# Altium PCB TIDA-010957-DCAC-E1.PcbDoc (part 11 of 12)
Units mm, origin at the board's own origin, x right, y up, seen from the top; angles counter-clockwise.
Board outline 300 x 300 mm, 4 copper layers (Top Layer, Layer 1, Layer 2, Bottom Layer), stack 1.787 mm thick; 1159 components, 619 nets, 3431 pads, 2942 vias.
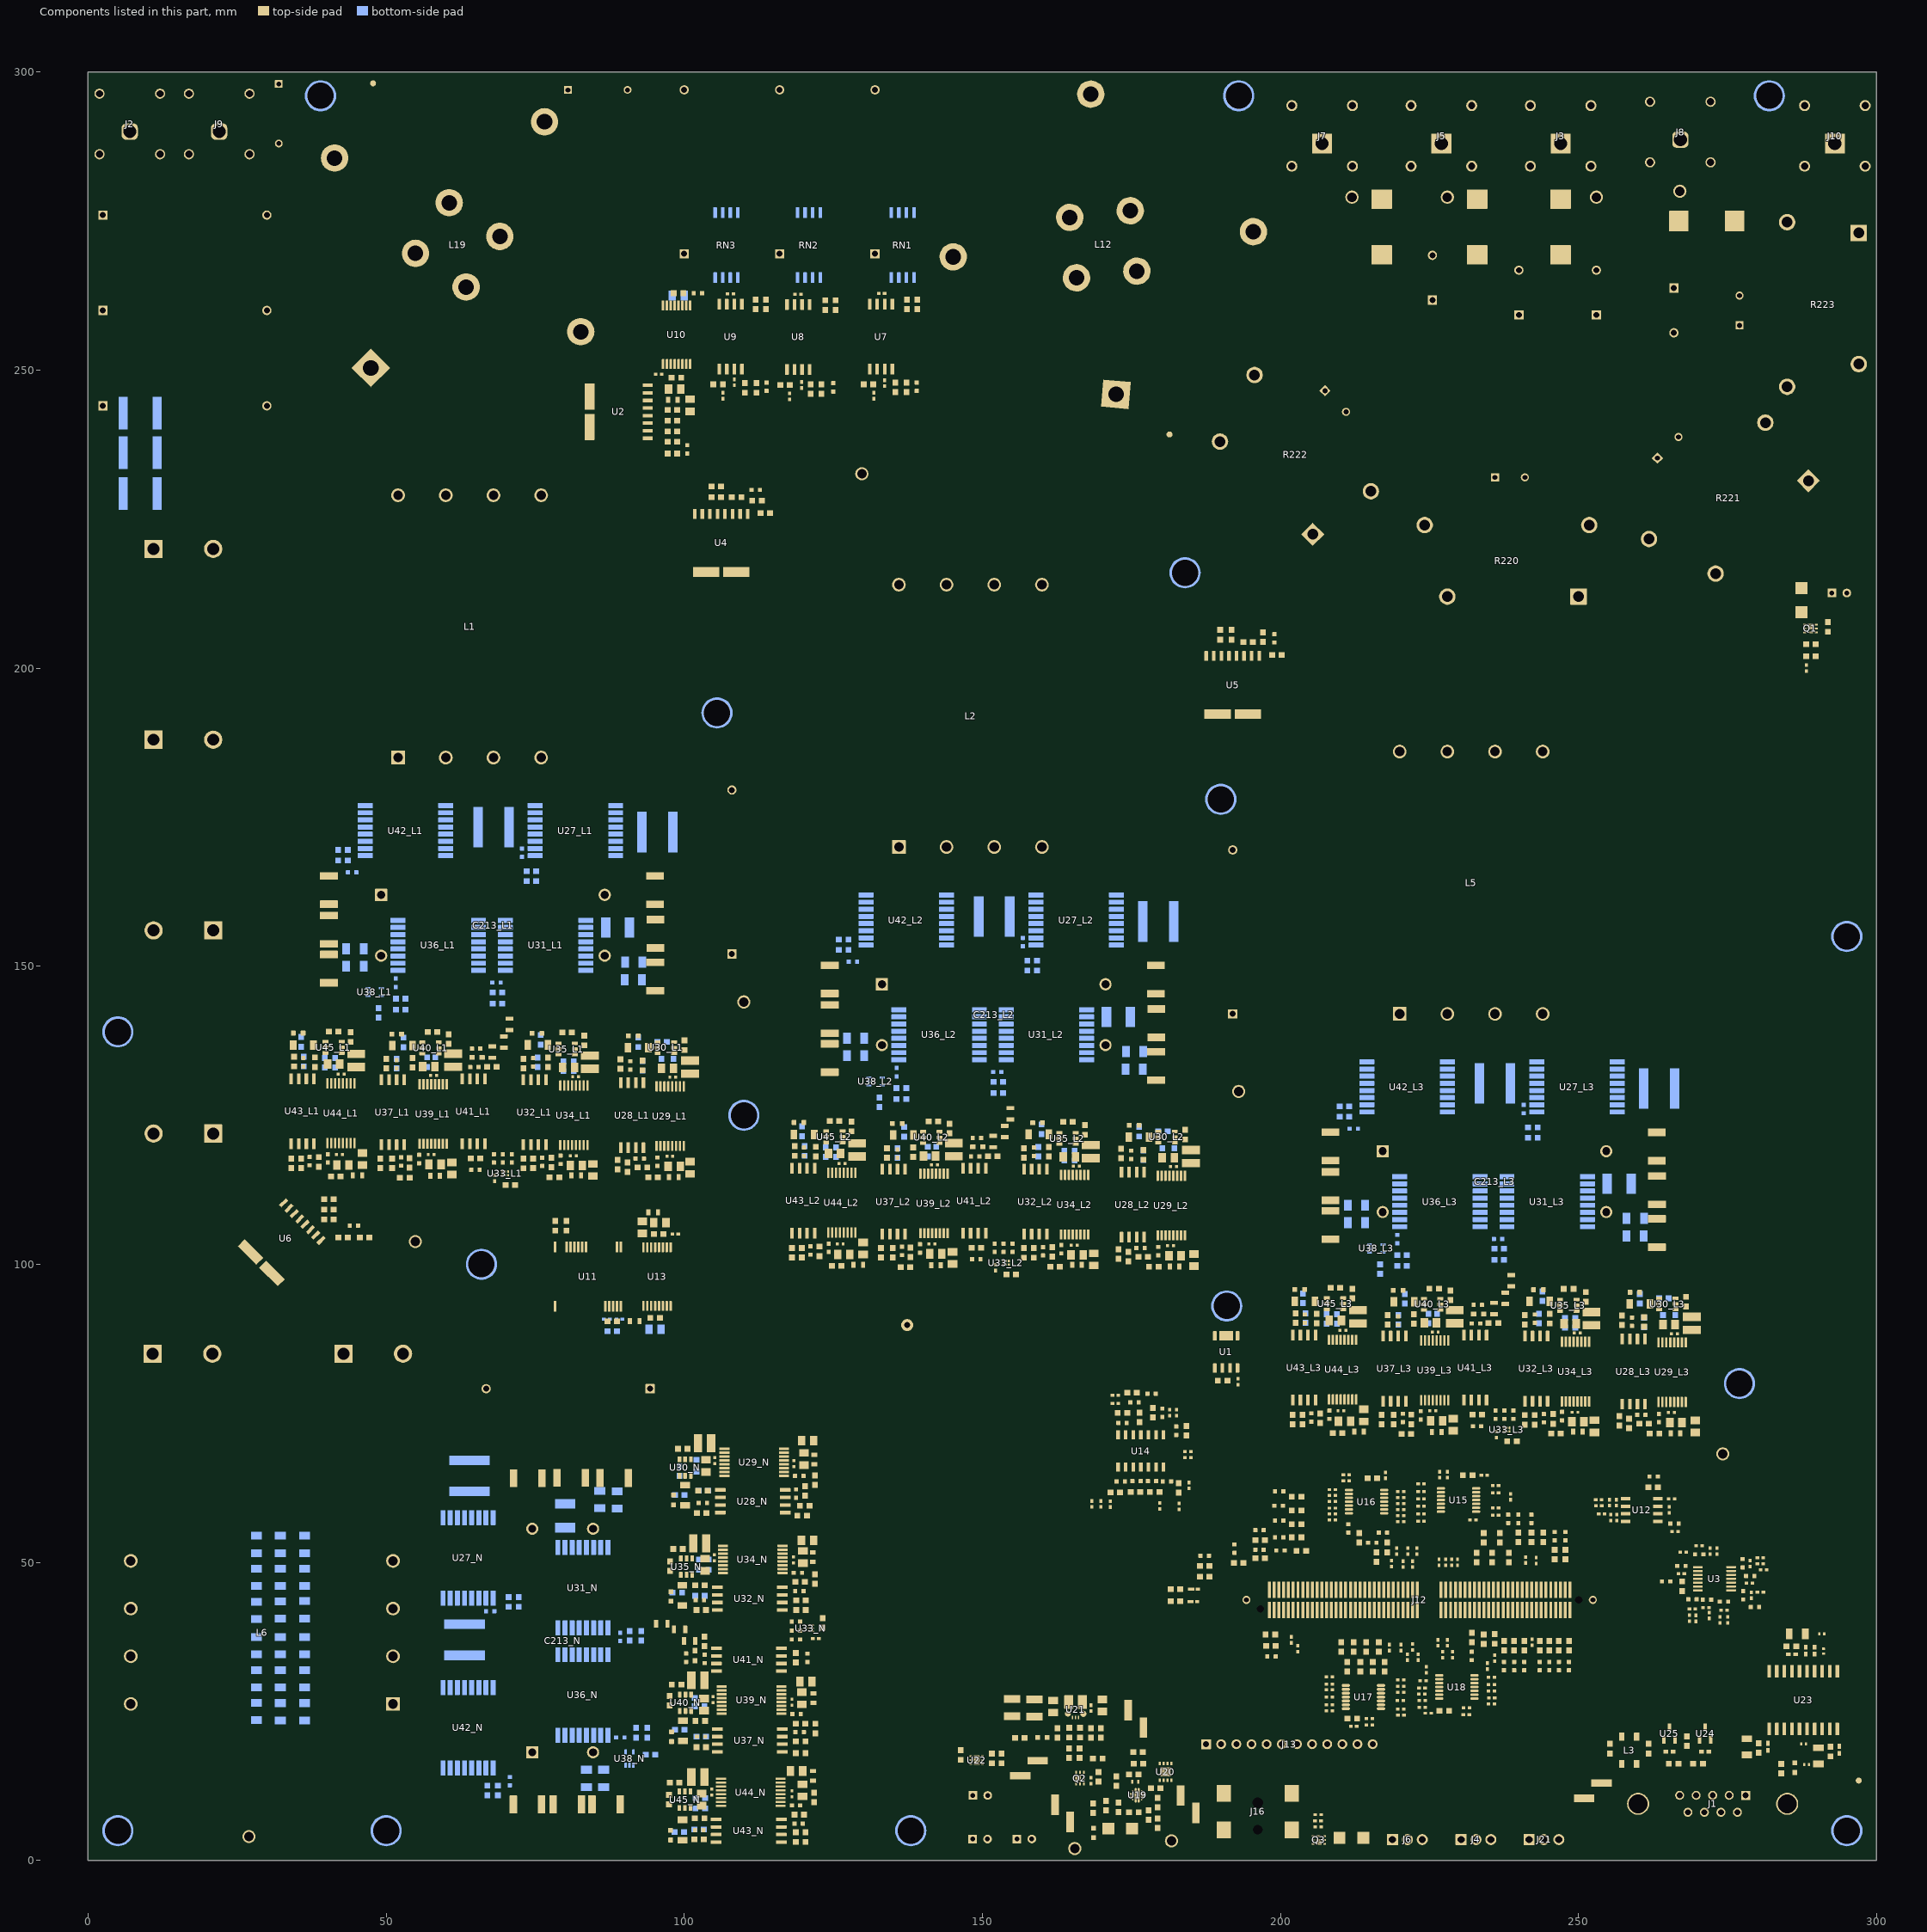
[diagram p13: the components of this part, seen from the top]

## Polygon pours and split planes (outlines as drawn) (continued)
NetC213_L1_2 on Bottom Layer "NONET_L-01_P-001" (solid, pour order 326): 88.1,159.3 88.1,153.9 87.8,153.6 85.6,153.6 85.6,159.3
VDC+ on Bottom Layer "NONET_L-01_P-001" (solid, pour order 325): 91.6,179.5 93.6,179.5 93.9,179.2 93.9,168.7 93.8,168.6 91.5,168.6
NetC213_L1_2 on Bottom Layer "NONET_L-01_P-001" (solid, pour order 324): 70.1,179 69.8,178.7 69.8,170.2 70.1,169.9 71.3,169.9 73.5,172.1 73.5,179
NetC213_L1_1 on Bottom Layer "NONET_L-01_P-001" (solid, pour order 323): 63.6,179 66,179 66.6,178.4 66.6,169.1 63.6,166.1
I_PCC_L3- on Bottom Layer "BOTTOM_LAYER_I_PCC_L3-_P316" (solid, remove dead copper, pour order 316): 194.1,187 193.7,187.4 192.6,187.4 192.6,192.4 194.1,192.4 250.1,192.4 250.1,183.9 194.1,183.9
GND on Bottom Layer "NONET_L-01_P-001" (solid, pour order 311): 42 vertices, not listed, extent 92.9,72.7 299.7,275.5
NetMP12_1 on Bottom Layer "BOTTOM_LAYER_NETMP12_1_P129" (solid, remove dead copper, pour order 129): 187.9,88.4 187.9,97.3 193.9,97.3 193.9,88.4
VDC-_REF on Bottom Layer "NONET_L-01_P-001" (solid, pour order 317): 26.5,23 27.6,24.1 38,24.1 43.8,18.3 56.4,18.3 57.9,16.8 57.9,11.9 57,11 27.6,11 26.5,12.1
GRID_GND on Bottom Layer "NONET_L-01_P-001" (solid, pour order 315): 277.5,299.8 295.9,299.8 299.2,296.5 299.2,281 298.5,280.3 278.4,280.3 276.4,282.3 276.4,298.7
I_PCC_L2- on Bottom Layer "BOTTOM_LAYER_I_PCC_L2-_P314" (solid, remove dead copper, pour order 314): 106.6,216.5 118,216.5 119,217.5 162.6,217.5 162.6,211 106.6,211
NetL12_4 on Bottom Layer "BOTTOM_LAYER_NETL12_4_P082" (solid, remove dead copper, pour order 82): 257,224 257,220 260.5,216.5 272,228 249,251 232,251 198,285 177,285 172,280 172,273 188.9,273 193.5,277.6 198.8,277.6 235.4,241 240,241
NetL12_2 on Bottom Layer "BOTTOM_LAYER_NETL12_2_P081" (solid, remove dead copper, pour order 81): 172.5,263 172.5,270 201,270 237,234 237,221.5 220.5,221.5 220.5,241.5 199,263
I_PCC_L3+ on Bottom Layer "BOTTOM_LAYER_I_PCC_L3+_P059" (solid, remove dead copper, pour order 59): 19 vertices, not listed, extent 34,184.5 192,243
VDC-_REF on Bottom Layer "BOTTOM_LAYER_VDC-_REF_P047" (solid, remove dead copper, pour order 47): 63.5,14 64,13.5 64,9.5 57.5,9.5 56,11 56,18.3 63.5,18.3
NetC213_L2_1 on Bottom Layer "BOTTOM_LAYER_NETC213_L2_1_P219" (solid, remove dead copper, pour order 219): 131,135 131,134 130,134 130,135.5 130,147.5 132,149.5 137.5,149.5 140,152 140,163 141,164 149,164 149.995,163.005 149.995,153.495 140,143.5 140,135
SN_L2 on Bottom Layer "BOTTOM_LAYER_SN_L2_P220" (solid, remove dead copper, pour order 220): 148,148.5 155,148.5 157.9,145.6 157.9,133.5 145.8,133.5 145.8,146.3
NetC213_L2_2 on Bottom Layer "BOTTOM_LAYER_NETC213_L2_2_P221" (solid, remove dead copper, pour order 221): 18 vertices, not listed, extent 154.191,133.356 172.5,164
VDC+ on Bottom Layer "BOTTOM_LAYER_VDC+_P222" (solid, remove dead copper, pour order 222): 171.5,164.5 177.5,164.5 177.5,154.508 179,153.008 179,148 174.6,148 169.3,153.3 169.3,162.3
NetC213_L2_2 on Bottom Layer "BOTTOM_LAYER_NETC213_L2_2_P223" (solid, remove dead copper, pour order 223): 173.244,131.265 174.732,131.265 174.724,131.273 174.724,137.622 172.611,137.622 172.25,137.983 171.659,137.392 171.659,134.703 170.733,133.776
NetD8_L2_2 on Bottom Layer "BOTTOM_LAYER_NETD8_L2_2_P224" (solid, remove dead copper, pour order 224): 177.87,136.861 177.87,132.515 177.876,132.521 182.163,132.521 182.163,131.53 182.118,131.575 176.231,131.575 176.231,136.823 176.269,136.861
NetC213_L2_1 on Bottom Layer "BOTTOM_LAYER_NETC213_L2_1_P225" (solid, remove dead copper, pour order 225): 174,144.5 176.5,144.5 176.5,139 174,139
VDC-_REF on Bottom Layer "BOTTOM_LAYER_VDC-_REF_P226" (solid, remove dead copper, pour order 226): 181.5,164 186.4,164 186.4,153.5 181.5,153.5
NetD13_L2_1 on Bottom Layer "BOTTOM_LAYER_NETD13_L2_1_P227" (solid, remove dead copper, pour order 227): 128,139.5 126.5,139.5 126.5,131.5 128,131.5
VDC-_REF on Bottom Layer "BOTTOM_LAYER_VDC-_REF_P228" (solid, remove dead copper, pour order 228): 129,158 128.5,157.5 124.5,157.5 124.5,164 126,165.5 133.3,165.5 133.3,158
+12V_OUT on Bottom Layer "NONET_L-01_P-001" (solid, pour order 295): 178.3,24.4 179.8,22.9 179.8,16.5 182,14.3 182,11.5 178.594,8.094 168.8,8.094 168.8,24.4
VDC-_REF on Bottom Layer "BOTTOM_LAYER_VDC-_REF_P273" (solid, remove dead copper, pour order 273): 213,130 212.5,129.5 208.5,129.5 208.5,136 210,137.5 217.2,137.5 217.2,130
NetD13_L3_1 on Bottom Layer "BOTTOM_LAYER_NETD13_L3_1_P272" (solid, remove dead copper, pour order 272): 212,111.5 210.5,111.5 210.5,103.5 212,103.5
VDC-_REF on Bottom Layer "BOTTOM_LAYER_VDC-_REF_P271" (solid, remove dead copper, pour order 271): 265.5,136 271.2,136 271.2,125.5 265.5,125.5
NetC213_L3_1 on Bottom Layer "BOTTOM_LAYER_NETC213_L3_1_P270" (solid, remove dead copper, pour order 270): 258,116.5 260.5,116.5 260.5,111 258,111
NetD8_L3_2 on Bottom Layer "BOTTOM_LAYER_NETD8_L3_2_P269" (solid, remove dead copper, pour order 269): 261.87,108.861 261.87,104.515 261.876,104.521 266.163,104.521 266.163,103.53 266.118,103.575 260.231,103.575 260.231,108.823 260.269,108.861
NetC213_L3_2 on Bottom Layer "BOTTOM_LAYER_NETC213_L3_2_P268" (solid, remove dead copper, pour order 268): 257.244,103.265 258.732,103.265 258.724,103.273 258.724,109.622 256.611,109.622 256.25,109.983 255.659,109.392 255.659,106.703 254.733,105.776
VDC+ on Bottom Layer "BOTTOM_LAYER_VDC+_P267" (solid, remove dead copper, pour order 267): 254.4,136.5 261.5,136.5 261.5,126.508 263,125.008 263,120 259.476,120 253.3,126.176 253.3,135.4
NetC213_L3_2 on Bottom Layer "BOTTOM_LAYER_NETC213_L3_2_P266" (solid, remove dead copper, pour order 266): 18 vertices, not listed, extent 238.191,105.356 256.5,136
SN_L3 on Bottom Layer "BOTTOM_LAYER_SN_L3_P265" (solid, remove dead copper, pour order 265): 232,120.5 239,120.5 242,117.5 242,105.5 229.9,105.5 229.9,118.4
NetC213_L3_1 on Bottom Layer "BOTTOM_LAYER_NETC213_L3_1_P264" (solid, remove dead copper, pour order 264): 215,107 215,106 214,106 214,107.5 214,119.5 216,121.5 221.5,121.5 224,124 224,135 225,136 233,136 233.995,135.005 233.995,125.495 223.5,115 223.5,107
VDC-_REF on Bottom Layer "BOTTOM_LAYER_VDC-_REF_P188" (solid, remove dead copper, pour order 188): 45,173 44.5,172.5 40.5,172.5 40.5,179 41.6,180.1 49.3,180.1 49.3,173
NetD13_L1_1 on Bottom Layer "BOTTOM_LAYER_NETD13_L1_1_P187" (solid, remove dead copper, pour order 187): 44,154.5 42.5,154.5 42.5,146.5 44,146.5
VDC-_REF on Bottom Layer "BOTTOM_LAYER_VDC-_REF_P186" (solid, remove dead copper, pour order 186): 97.5,179 102,179 102,168.5 97.5,168.5
NetC213_L1_1 on Bottom Layer "BOTTOM_LAYER_NETC213_L1_1_P185" (solid, remove dead copper, pour order 185): 90,159.5 92.5,159.5 92.5,154 90,154
NetD8_L1_2 on Bottom Layer "BOTTOM_LAYER_NETD8_L1_2_P184" (solid, remove dead copper, pour order 184): 93.87,151.861 93.87,147.515 93.876,147.521 98.163,147.521 98.163,146.53 98.118,146.575 92.231,146.575 92.231,151.823 92.269,151.861
NetC213_L1_2 on Bottom Layer "BOTTOM_LAYER_NETC213_L1_2_P183" (solid, remove dead copper, pour order 183): 89.244,146.265 90.732,146.265 90.724,146.273 90.724,152.622 88.611,152.622 88.25,152.983 87.659,152.392 87.659,149.703 86.733,148.776
VDC+ on Bottom Layer "BOTTOM_LAYER_VDC+_P182" (solid, remove dead copper, pour order 182): 87.5,179.5 91.7,179.5 91.7,170.9 95,167.6 95,163 91.476,163 85.2,169.276 85.2,177.2
NetC213_L1_2 on Bottom Layer "BOTTOM_LAYER_NETC213_L1_2_P181" (solid, remove dead copper, pour order 181): 17 vertices, not listed, extent 71.8,148.356 88.5,179
SN_L1 on Bottom Layer "BOTTOM_LAYER_SN_L1_P180" (solid, remove dead copper, pour order 180): 64,163.5 71,163.5 73.8,160.7 73.8,148.5 61.8,148.5 61.8,161.3
NetC213_L1_1 on Bottom Layer "BOTTOM_LAYER_NETC213_L1_1_P179" (solid, remove dead copper, pour order 179): 47,150 47,149 46,149 46,150.5 46,162.5 48,164.5 53.5,164.5 56,167 56,178 57,179 63.9,179 63.9,166.4 54.8,157.3 54.8,150
NetC75_1 on Bottom Layer "NONET_L-01_P-001" (solid, pour order 141): 99.608,263.371 101.829,263.371 101.971,263.229 101.971,261.721 99.421,261.721 99.4,261.7 99.4,263.371
V_PCC_N on Bottom Layer "NONET_L-01_P-001" (solid, pour order 138): 96,263.8 98.7,263.8 98.8,263.7 98.8,261.8 98.6,261.6 96,261.6
Middle_Point on Bottom Layer "Bottom Layer-Middle_Point" (solid, remove dead copper, pour order 120): 24 vertices, not listed, extent 9,36.85 45,246
NetF2_1 on Bottom Layer "BOTTOM_LAYER_NETF2_1_P087" (solid, remove dead copper, pour order 87): 230.5,271 244,271 244,265 257,252 274,252 283.5,242.5 283.5,239.5 273,239.5 272,240.5 268.5,244 258.5,244 238.5,264 230.5,264
NetL12_6 on Bottom Layer "BOTTOM_LAYER_NETL12_6_P080" (solid, remove dead copper, pour order 80): 18 vertices, not listed, extent 153.5,245 201,280
I_PCC_L1+ on Bottom Layer "BOTTOM_LAYER_I_PCC_L1+_P067" (solid, remove dead copper, pour order 67): 60.5,265.5 62,267 64.7,267 66.9,264.8 66.9,262.4 62.5,258 27.5,258 27.5,261 56,261
I_PCC_L2+ on Bottom Layer "BOTTOM_LAYER_I_PCC_L2+_P056" (solid, remove dead copper, pour order 56): 21 vertices, not listed, extent 65.5,210 106,276
I_PCC_N- on Bottom Layer "BOTTOM_LAYER_I_PCC_N-_P042" (solid, remove dead copper, pour order 42): 1.5,22 7.5,22 9.5,24 9.5,52 7.5,54 7.5,80.5 1.5,80.5
VDC+ on Bottom Layer "BOTTOM_LAYER_VDC+_P041" (solid, remove dead copper, pour order 41): 58.5,62.5 58.5,53.8 26.5,53.8 26.5,62.5
VDC-_REF on Bottom Layer "BOTTOM_LAYER_VDC-_REF_P040" (solid, remove dead copper, pour order 40): 26.5,20.5 26.5,24.2 38,24.2 38,20.5
NetR1_1 on Bottom Layer "BOTTOM_LAYER_NETR1_1_P039" (solid, remove dead copper, pour order 39): 26.5,48.3 26.5,52.2 38,52.2 38,48.3
NetR4_1 on Bottom Layer "BOTTOM_LAYER_NETR4_1_P038" (solid, remove dead copper, pour order 38): 26.5,42.8 26.5,46.7 38,46.7 38,42.8
NetR10_1 on Bottom Layer "BOTTOM_LAYER_NETR10_1_P036" (solid, remove dead copper, pour order 36): 26.5,31.308 26.5,35.228 38,35.228 38,31.308
NetR13_1 on Bottom Layer "BOTTOM_LAYER_NETR13_1_P035" (solid, remove dead copper, pour order 35): 26.5,25.8 26.5,29.7 38,29.7 38,25.8
NetD13_N_1 on Bottom Layer "BOTTOM_LAYER_NETD13_N_1_P034" (solid, remove dead copper, pour order 34): 82,13 82,11.5 90,11.5 90,13
VDC-_REF on Bottom Layer "BOTTOM_LAYER_VDC-_REF_P029" (solid, remove dead copper, pour order 29): 57.5,66.5 57.5,71.1 68,71.1 68,66.5
NetC213_N_2 on Bottom Layer "BOTTOM_LAYER_NETC213_N_2_P007" (solid, remove dead copper, pour order 7): 17 vertices, not listed, extent 57.5,39.191 88.7,57.5
NetC213_N_1 on Bottom Layer "BOTTOM_LAYER_NETC213_N_1_P026" (solid, remove dead copper, pour order 26): 77,59 77,61.5 82.5,61.5 82.5,59
NetD8_N_2 on Bottom Layer "BOTTOM_LAYER_NETD8_N_2_P017" (solid, remove dead copper, pour order 17): 84.639,62.87 88.985,62.87 88.979,62.876 88.979,67.163 89.97,67.163 89.925,67.118 89.925,61.231 84.677,61.231 84.639,61.269
NetC213_N_2 on Bottom Layer "BOTTOM_LAYER_NETC213_N_2_P016" (solid, remove dead copper, pour order 16): 90.235,58.244 90.235,59.732 90.227,59.724 83.878,59.724 83.878,57.611 83.517,57.25 84.108,56.659 86.797,56.659 87.724,55.733
VDC+ on Bottom Layer "BOTTOM_LAYER_VDC+_P015" (solid, remove dead copper, pour order 15): 57,54.5 57,62.5 66.992,62.5 68.492,64 73.5,64 73.5,60.476 66.824,53.8 57.7,53.8
SN_LN on Bottom Layer "BOTTOM_LAYER_SN_LN_P002" (solid, remove dead copper, pour order 2): 73,33 73,40 75.7,42.7 88,42.7 88,31.2 74.8,31.2
NetC213_N_1 on Bottom Layer "BOTTOM_LAYER_NETC213_N_1_P001" (solid, remove dead copper, pour order 1): 86.5,16 87.5,16 87.5,15 74,15 72,17 72,22.5 69.5,25 58.5,25 57.5,26 57.5,34 58.495,34.995 68.005,34.995 78.3,24.7 86.5,24.7
GND on Top Layer "NONET_L-01_P-001" (solid, pour order 309): 40 vertices, not listed, extent 92.9,72.7 299.7,275.5
GND on Top Layer "NONET_L-01_P-001" (solid, pour order 308): 26 vertices, not listed, extent 32.1,0.6 299.9,121
NetF3_1 on Top Layer "TOP_LAYER_NETF3_1_P085" (solid, remove dead copper, pour order 85): 218.5,227.5 222.5,231.5 225,231.5 226.5,233 226.5,251 223,254.5 223,268 221,270 210.5,270 208,267.5 208,254.5 210.5,252 210.5,227.5
NetL12_2 on Top Layer "TOP_LAYER_NETL12_2_P383" (solid, remove dead copper, pour order 383): 221,226.5 232,226.5 232,234 237,234 237,222 221,222
NetL12_4 on Top Layer "TOP_LAYER_NETL12_4_P382" (solid, remove dead copper, pour order 382): 263,233 259,237 261,239 264,236 267,233 271,229 271,227 264,220 260,220 260,224 263,227
NetL12_2 on Top Layer "TOP_LAYER_NETL12_2_P381" (solid, remove dead copper, pour order 381): 173,270 173,263 181,263 181,270
NetL12_4 on Top Layer "TOP_LAYER_NETL12_4_P380" (solid, remove dead copper, pour order 380): 172,273 172,280 174,282 180,282 180,273
GRID_GND on Top Layer "TOP_LAYER_GRID_GND_P378" (solid, remove dead copper, pour order 378): 277,299 277,286 296,286 296,299
I_PCC_L1+ on Top Layer "TOP_LAYER_I_PCC_L1+_P053" (solid, remove dead copper, pour order 53): 84.9,243.4 71.6,243.4 60,255 60,265 62,267 65,267 67,265 67,257 76,248 84.9,248
SN_L2 on Top Layer "TOP_LAYER_SN_L2_P230" (solid, remove dead copper, pour order 230): 155.6,159.6 161.665,165.665 162.25,165.665 162.25,172.165 132.75,172.165 132.75,166.165 138.75,166.165 146.9,158.015 146.9,143.165 155.6,143.165
SN_L3 on Top Layer "TOP_LAYER_SN_L3_P252" (solid, remove dead copper, pour order 252): 239.6,131.6 246.25,138.25 246.25,144.165 216.75,144.165 216.75,138.165 222.75,138.165 230.9,130.015 230.9,115.165 239.6,115.165
I_PCC_L2- on Top Layer "Top Layer-I_PCC_L2-" (solid, remove dead copper, pour order 363): 106.5,211 115,211 116,212 163,212 163,218 124.5,218 123,216.5 106.5,216.5
GRID_GND_1 on Top Layer "TOP_LAYER_GRID_GND_1_P362" (solid, remove dead copper, pour order 362): 30.5,299.5 30.5,296.6 35.1,292 42,292 44.5,294.5 44.5,299.5
I_PCC_L3+ on Top Layer "Top Layer-I_PCC_L3+" (solid, remove dead copper, pour order 361): 23 vertices, not listed, extent 27.5,235.5 65,282
I_PCC_L3- on Top Layer "TOP_LAYER_I_PCC_L3-_P061" (solid, remove dead copper, pour order 61): 210,184 247,184 249,186 249,191.5 215.5,191.5 214,193 192.5,193 192.5,191.5 192.5,193.5 192.5,185.5 194,184
NetMP12_1 on Top Layer "TOP_LAYER_NETMP12_1_P130" (solid, remove dead copper, pour order 130): 187.9,87.3 187.9,97.3 193.9,97.3 193.9,87.3
GND on Top Layer "TOP_LAYER_GND_P189" (solid, remove dead copper, pour order 189): 125.9,106.2 130.7,106.2 130.7,104.2 128.505,102.005 126.704,102.005 126.704,103.536 125.9,104.339
GND on Top Layer "TOP_LAYER_GND_P190" (solid, remove dead copper, pour order 190): 141.2,106.1 146.8,106.1 146.8,104.239 144.657,102.096 142.1,102.096 142.1,103.539 141.2,104.439
GND on Top Layer "TOP_LAYER_GND_P191" (solid, remove dead copper, pour order 191): 165,105.9 169.8,105.9 169.8,102.9 168.733,101.833 165.894,101.833 165.894,103.146 165,104.039
GND on Top Layer "TOP_LAYER_GND_P192" (solid, remove dead copper, pour order 192): 181,105.739 186,105.739 186,102.039 182.7,102.039 182.7,102.339 181,104.039
GND_S4_GaN_L2 on Top Layer "TOP_LAYER_GND_S4_GAN_L2_P193" (solid, remove dead copper, pour order 193): 123.353,115.85 121.353,115.85 121.353,118.85 123.353,118.85 123.353,119.35 124.853,119.35 124.853,117.85 126.353,116.35 126.853,116.35 126.853,114.85 123.353,114.85
5V_S4_GaN_L2 on Top Layer "TOP_LAYER_5V_S4_GAN_L2_P194" (solid, remove dead copper, pour order 194): 126.353,118.85 130.353,118.85 130.353,114.85 127.353,114.85 127.353,116.35 126.853,116.85 126.353,116.85
GND_S3_GaN_L2 on Top Layer "TOP_LAYER_GND_S3_GAN_L2_P195" (solid, remove dead copper, pour order 195): 141.353,116.35 142.353,116.35 142.353,114.85 138.853,114.85 138.853,116.85 137.353,116.85 137.353,118.85 138.853,118.85 139.353,119.35 140.353,119.35 140.353,117.35 141.353,117.35
5V_S3_GaN_L2 on Top Layer "TOP_LAYER_5V_S3_GAN_L2_P196" (solid, remove dead copper, pour order 196): 142.853,114.85 142.853,116.35 142.353,116.85 142.353,118.85 144.853,118.85 144.853,114.85
GND_S2_GaN_L2 on Top Layer "TOP_LAYER_GND_S2_GAN_L2_P197" (solid, remove dead copper, pour order 197): 164.853,116.35 165.853,116.35 165.853,114.35 162.853,114.35 162.353,114.85 162.353,118.85 164.353,118.85 164.353,116.85
GND_S1_GaN_L2 on Top Layer "TOP_LAYER_GND_S1_GAN_L2_P198" (solid, remove dead copper, pour order 198): 180.853,118.85 180.853,116.35 181.853,116.35 181.853,113.85 178.853,113.85 178.7,114.003 178.7,116.003 177.853,116.85 177.853,118.85
5V_S1_GaN_L2 on Top Layer "TOP_LAYER_5V_S1_GAN_L2_P199" (solid, remove dead copper, pour order 199): 182.353,117.85 184.853,117.85 184.853,114.25 184.653,114.05 182.353,114.05 182.353,117.95
NetD14_L2_1 on Top Layer "TOP_LAYER_NETD14_L2_1_P200" (solid, remove dead copper, pour order 200): 126.497,146.175 126.497,143.175 122.497,143.175 122.497,146.175
NetD13_L2_2 on Top Layer "TOP_LAYER_NETD13_L2_2_P201" (solid, remove dead copper, pour order 201): 126.497,139.175 126.497,136.175 122.497,136.175 122.497,139.175
NetD13_L2_1 on Top Layer "TOP_LAYER_NETD13_L2_1_P202" (solid, remove dead copper, pour order 202): 126.497,133.675 126.497,134.175 127.997,134.175 127.997,131.675 122.497,131.675 122.497,133.675
VDC-_REF on Top Layer "TOP_LAYER_VDC-_REF_P203" (solid, remove dead copper, pour order 203): 122.497,149.675 126.497,149.675 126.497,156.175 128.997,158.675 128.997,163.675 124.497,163.675 122.497,161.675
NetD8_L2_2 on Top Layer "TOP_LAYER_NETD8_L2_2_P204" (solid, remove dead copper, pour order 204): 177.475,131.975 178,132.5 182.505,132.5 182.505,129.5 177.475,129.5
NetD8_L2_1 on Top Layer "TOP_LAYER_NETD8_L2_1_P205" (solid, remove dead copper, pour order 205): 177.975,138.5 183.005,138.5 183.005,135 177.975,135
NetD7_L2_2 on Top Layer "TOP_LAYER_NETD7_L2_2_P206" (solid, remove dead copper, pour order 206): 177.975,144.975 178.5,145.5 183.005,145.5 183.005,142.5 177.975,142.5
VDC+ on Top Layer "TOP_LAYER_VDC+_P207" (solid, remove dead copper, pour order 207): 173,154 179.5,154 182,151.5 182,149.5 178.5,149.5 177.5,148.5 175,148.5 173,150.5
NetC213_L2_2 on Top Layer "TOP_LAYER_NETC213_L2_2_P208" (solid, remove dead copper, pour order 208): 161,155.5 161,152.5 168,145.5 172.3,145.5 172.3,148.2 171,149.5 167.6,149.5 164.5,152.6 164.5,155.5
I_PCC_L3+ on Top Layer "TOP_LAYER_I_PCC_L3+_P307" (solid, remove dead copper, pour order 307): 191.791,193 191.791,185.165 184.791,185.165 184.791,193
VDC-_REF on Top Layer "NONET_L-01_P-001" (solid, pour order 306): 95.1,93.9 97.7,93.9 97.9,93.7 97.9,90.6 97.642,90.342 95.658,90.342 95.4,90.6 95.4,91.8 94.9,92.3 94.9,93.7
GND on Top Layer "NONET_L-01_P-001" (solid, pour order 305): 92.3,105.9 93.8,105.9 94.2,106.3 94.2,107.7 95.243,107.7 95.5,107.443 95.5,104.2 96,103.7 96,102.2 95.8,102 92.2,102 91.7,102.5 91.7,105.3
GND on Top Layer "NONET_L-01_P-001" (solid, pour order 304): 204.9,6.2 204.943,6.243 206.187,6.243 206.187,4.856 206.7,4.343 206.7,4 206.6,3.9 205,3.9 204.9,4
GND on Top Layer "NONET_L-01_P-001" (solid, pour order 303): 153.6,25.4 163.4,25.4 163.8,25 164.8,25 164.8,23.8 164.5,23.5 153.6,23.5
GND on Top Layer "NONET_L-01_P-001" (solid, pour order 302): 145.8,17.4 147,17.4 147.4,17 148.3,17 148.7,17.4 149.4,17.4 150,16.8 153.425,16.8 153.7,16.525 153.7,15.9 145.912,15.9 145.6,16.212 145.6,17.2
5V on Top Layer "NONET_L-01_P-001" (solid, pour order 294): 160.708,21.1 163.2,21.1 163.3,21 163.3,16.6 162.8,16.1 157.6,16.1 157.3,16.4 157.3,17.8 158,18.5 160.1,18.5 160.4,18.8 160.4,20.792
5V on Top Layer "NONET_L-01_P-001" (solid, pour order 293): 153.9,28.4 164.6,28.4 165.2,27.8 165.2,25.8 165,25.6 164.1,25.6 164.1,25.952 163.852,26.2 153.4,26.2 153.2,26.4 153.2,27.7
3V3 on Top Layer "NONET_L-01_P-001" (solid, pour order 291): 149.3,22 149.6,21.7 149.6,18.649 148.273,17.322 147.738,17.322 147.152,17.908 145.144,17.908 144.909,18.143 144.909,21.009 145.9,22
GNDP on Top Layer "NONET_L-01_P-001" (solid, pour order 285): 179.8,17 181.721,17 182.2,16.521 182.2,16 182.1,15.9 179.4,15.9 179.3,16 179.3,16.5
GNDP on Top Layer "NONET_L-01_P-001" (solid, pour order 284): 24 vertices, not listed, extent 166.852,12.886 175.9,16.725
GNDP on Top Layer "NONET_L-01_P-001" (solid, pour order 283): 174.8,8.9 175.1,8.6 175.1,7.6 174.9,7.4 170.6,7.4 170.2,7.8 170.2,8.9
GNDP on Top Layer "NONET_L-01_P-001" (solid, pour order 282): 200.2,12.8 200.3,12.9 203,12.9 203.4,12.5 203.4,1.7 202.4,0.7 200.9,0.7 200.2,1.4 200.2,12.8
FAN_SN on Top Layer "NONET_L-01_P-001" (solid, pour order 280): 41 vertices, not listed, extent 205,0.2 247.8,4.7
DCDC_VIN on Top Layer "NONET_L-01_P-001" (solid, pour order 279): 166.9,25.1 171.8,25.1 173.8,27.1 175.1,27.1 175.2,27 175.2,23.7 175,23.5 171.764,23.5 171.064,24.2 166.9,24.2
12V_FET_DRAIN on Top Layer "NONET_L-01_P-001" (solid, pour order 278): 166.5,15.1 166.5,12.2 168.5,10.2 169.1,10.2 169.1,9.65 169.087,9.636 169.087,9.187 169,9.1 168.2,9.1 165.5,11.8 165.5,15.1
VIN_PWR on Top Layer "NONET_L-01_P-001" (solid, pour order 277): 18 vertices, not listed, extent 175.7,8.9 184,15
AUX_IN_PWR on Top Layer "NONET_L-01_P-001" (solid, pour order 276): 191.3,12.6 191.7,12.2 191.7,3.6 191.3,3.2 186.3,3.2 185.2,4.3 185.2,11.4 186.4,12.6 185.2,11.4 186.4,12.6
NetC213_L3_2 on Top Layer "TOP_LAYER_NETC213_L3_2_P251" (solid, remove dead copper, pour order 251): 245,127.5 245,124.5 252,117.5 256.4,117.5 256.4,120.1 255,121.5 251.6,121.5 248.2,124.9 248.2,127.5
VDC+ on Top Layer "TOP_LAYER_VDC+_P250" (solid, remove dead copper, pour order 250): 257,126 263.5,126 266,123.5 266,121.5 262.5,121.5 261.5,120.5 259,120.5 257,122.5
NetD7_L3_2 on Top Layer "TOP_LAYER_NETD7_L3_2_P249" (solid, remove dead copper, pour order 249): 261.975,116.975 262.5,117.5 267.005,117.5 267.005,114.5 261.975,114.5
NetD8_L3_1 on Top Layer "TOP_LAYER_NETD8_L3_1_P248" (solid, remove dead copper, pour order 248): 261.975,110.5 267.005,110.5 267.005,107 261.975,107
NetD8_L3_2 on Top Layer "TOP_LAYER_NETD8_L3_2_P247" (solid, remove dead copper, pour order 247): 261.475,103.975 262,104.5 266.505,104.5 266.505,101.5 261.475,101.5
VDC-_REF on Top Layer "TOP_LAYER_VDC-_REF_P246" (solid, remove dead copper, pour order 246): 206.497,121.675 210.497,121.675 210.497,128.175 212.997,130.675 212.997,135.675 208.497,135.675 206.497,133.675
NetD13_L3_1 on Top Layer "TOP_LAYER_NETD13_L3_1_P245" (solid, remove dead copper, pour order 245): 210.497,105.675 210.497,106.175 211.997,106.175 211.997,103.675 206.497,103.675 206.497,105.675
NetD13_L3_2 on Top Layer "TOP_LAYER_NETD13_L3_2_P244" (solid, remove dead copper, pour order 244): 210.497,111.175 210.497,108.175 206.497,108.175 206.497,111.175
NetD14_L3_1 on Top Layer "TOP_LAYER_NETD14_L3_1_P243" (solid, remove dead copper, pour order 243): 210.497,118.175 210.497,115.175 206.497,115.175 206.497,118.175
5V_S1_GaN_L3 on Top Layer "TOP_LAYER_5V_S1_GAN_L3_P242" (solid, remove dead copper, pour order 242): 266.353,89.85 268.853,89.85 268.853,86.25 268.653,86.05 266.353,86.05 266.353,89.95
GND_S1_GaN_L3 on Top Layer "TOP_LAYER_GND_S1_GAN_L3_P241" (solid, remove dead copper, pour order 241): 264.853,90.85 264.853,88.35 265.853,88.35 265.853,85.85 262.853,85.85 262.353,86.35 262.353,88.35 261.853,88.85 261.853,90.85
5V_S2_GaN_L3 on Top Layer "TOP_LAYER_5V_S2_GAN_L3_P240" (solid, remove dead copper, pour order 240): 250.124,86.35 251.853,86.35 251.853,88.85 252.353,89.35 252.353,89.85 250.124,89.85
GND_S2_GaN_L3 on Top Layer "TOP_LAYER_GND_S2_GAN_L3_P239" (solid, remove dead copper, pour order 239): 248.853,88.35 249.853,88.35 249.853,86.35 246.853,86.35 246.353,86.85 246.353,90.85 248.353,90.85 248.353,88.85
5V_S3_GaN_L3 on Top Layer "TOP_LAYER_5V_S3_GAN_L3_P238" (solid, remove dead copper, pour order 238): 226.853,86.85 226.853,88.35 226.353,88.85 226.353,90.85 228.853,90.85 228.853,86.85
GND_S3_GaN_L3 on Top Layer "TOP_LAYER_GND_S3_GAN_L3_P237" (solid, remove dead copper, pour order 237): 225.353,88.35 226.353,88.35 226.353,86.85 222.853,86.85 222.853,88.85 221.353,88.85 221.353,90.85 222.853,90.85 223.353,91.35 224.353,91.35 224.353,89.35 225.353,89.35
5V_S4_GaN_L3 on Top Layer "TOP_LAYER_5V_S4_GAN_L3_P236" (solid, remove dead copper, pour order 236): 210.353,90.85 214.353,90.85 214.353,86.85 211.353,86.85 211.353,88.35 210.853,88.85 210.353,88.85
GND_S4_GaN_L3 on Top Layer "TOP_LAYER_GND_S4_GAN_L3_P235" (solid, remove dead copper, pour order 235): 207.353,87.85 205.353,87.85 205.353,90.85 207.353,90.85 207.353,91.35 208.853,91.35 208.853,89.85 210.353,88.35 210.853,88.35 210.853,86.85 207.353,86.85
GND on Top Layer "TOP_LAYER_GND_P234" (solid, remove dead copper, pour order 234): 265,77.739 270,77.739 270,74.039 266.7,74.039 266.7,74.339 265,76.039
GND on Top Layer "TOP_LAYER_GND_P233" (solid, remove dead copper, pour order 233): 249,77.9 253.8,77.9 253.8,74.9 252.733,73.833 249.894,73.833 249.894,75.146 249,76.039
GND on Top Layer "TOP_LAYER_GND_P232" (solid, remove dead copper, pour order 232): 225.2,78.1 230.8,78.1 230.8,76.239 228.657,74.096 226.1,74.096 226.1,75.539 225.2,76.439
GND on Top Layer "TOP_LAYER_GND_P231" (solid, remove dead copper, pour order 231): 209.9,78.2 214.7,78.2 214.7,76.2 212.505,74.005 210.704,74.005 210.704,75.536 209.9,76.339
SN_L1 on Top Layer "TOP_LAYER_SN_L1_P168" (solid, remove dead copper, pour order 168): 71.6,174.6 77.665,180.665 78.25,180.665 78.25,187.165 48.75,187.165 48.75,181.165 54.75,181.165 62.9,173.015 62.9,158.165 71.6,158.165
GND_S4_GaN_L1 on Top Layer "TOP_LAYER_GND_S4_GAN_L1_P151" (solid, remove dead copper, pour order 151): 39.353,130.85 37.353,130.85 37.353,133.85 39.353,133.85 39.353,134.35 40.853,134.35 40.853,132.85 42.353,131.35 42.853,131.35 42.853,129.85 39.353,129.85
5V_S4_GaN_L1 on Top Layer "TOP_LAYER_5V_S4_GAN_L1_P152" (solid, remove dead copper, pour order 152): 42.353,133.85 46.353,133.85 46.353,129.85 43.353,129.85 43.353,131.35 42.853,131.85 42.353,131.85
GND_S3_GaN_L1 on Top Layer "TOP_LAYER_GND_S3_GAN_L1_P153" (solid, remove dead copper, pour order 153): 57.353,131.35 58.353,131.35 58.353,129.85 54.853,129.85 54.853,131.85 53.353,131.85 53.353,133.85 54.853,133.85 55.353,134.35 56.353,134.35 56.353,132.35 57.353,132.35
5V_S3_GaN_L1 on Top Layer "TOP_LAYER_5V_S3_GAN_L1_P154" (solid, remove dead copper, pour order 154): 58.853,129.85 58.853,131.35 58.353,131.85 58.353,133.85 60.853,133.85 60.853,129.85
GND_S2_GaN_L1 on Top Layer "TOP_LAYER_GND_S2_GAN_L1_P155" (solid, remove dead copper, pour order 155): 80.853,131.35 81.853,131.35 81.853,129.35 78.853,129.35 78.353,129.85 78.353,133.85 80.353,133.85 80.353,131.85
5V_S2_GaN_L1 on Top Layer "TOP_LAYER_5V_S2_GAN_L1_P156" (solid, remove dead copper, pour order 156): 82.124,129.35 83.853,129.35 83.853,131.85 84.353,132.35 84.353,132.85 82.124,132.85
GND_S1_GaN_L1 on Top Layer "TOP_LAYER_GND_S1_GAN_L1_P157" (solid, remove dead copper, pour order 157): 96.853,133.85 96.853,131.35 97.853,131.35 97.853,128.85 94.853,128.85 94.353,129.35 94.353,131.35 93.853,131.85 93.853,133.85
5V_S1_GaN_L1 on Top Layer "TOP_LAYER_5V_S1_GAN_L1_P158" (solid, remove dead copper, pour order 158): 98.353,132.85 100.853,132.85 100.853,129.25 100.653,129.05 98.353,129.05 98.353,132.95
NetD14_L1_1 on Top Layer "TOP_LAYER_NETD14_L1_1_P159" (solid, remove dead copper, pour order 159): 42.497,161.175 42.497,158.175 38.497,158.175 38.497,161.175
NetD13_L1_2 on Top Layer "TOP_LAYER_NETD13_L1_2_P160" (solid, remove dead copper, pour order 160): 42.497,154.175 42.497,151.175 38.497,151.175 38.497,154.175
NetD13_L1_1 on Top Layer "TOP_LAYER_NETD13_L1_1_P161" (solid, remove dead copper, pour order 161): 42.497,148.675 42.497,149.175 43.997,149.175 43.997,146.675 38.497,146.675 38.497,148.675
VDC-_REF on Top Layer "TOP_LAYER_VDC-_REF_P162" (solid, remove dead copper, pour order 162): 38.497,164.675 42.497,164.675 42.497,171.175 44.997,173.675 44.997,178.675 40.497,178.675 38.497,176.675
NetD8_L1_2 on Top Layer "TOP_LAYER_NETD8_L1_2_P163" (solid, remove dead copper, pour order 163): 93.475,146.975 94,147.5 98.505,147.5 98.505,144.5 93.475,144.5
NetD8_L1_1 on Top Layer "TOP_LAYER_NETD8_L1_1_P164" (solid, remove dead copper, pour order 164): 93.975,153.5 99.005,153.5 99.005,150 93.975,150
NetD7_L1_2 on Top Layer "TOP_LAYER_NETD7_L1_2_P165" (solid, remove dead copper, pour order 165): 93.975,159.975 94.5,160.5 99.005,160.5 99.005,157.5 93.975,157.5
VDC+ on Top Layer "TOP_LAYER_VDC+_P166" (solid, remove dead copper, pour order 166): 89,169 95.5,169 98,166.5 98,164.5 94.5,164.5 93.5,163.5 91,163.5 89,165.5
NetC213_L1_2 on Top Layer "TOP_LAYER_NETC213_L1_2_P167" (solid, remove dead copper, pour order 167): 77,170.5 77,167.5 84,160.5 88.5,160.5 88.5,163 87,164.5 83.8,164.5 80.5,167.8 80.5,170.5
NetD8_N_2 on Top Layer "TOP_LAYER_NETD8_N_2_P018" (solid, remove dead copper, pour order 18): 89.525,62.475 89,63 89,67.505 92,67.505 92,62.475
NetD8_N_1 on Top Layer "TOP_LAYER_NETD8_N_1_P043" (solid, remove dead copper, pour order 43): 83,62.975 83,68.005 86.5,68.005 86.5,62.975
NetD7_N_2 on Top Layer "TOP_LAYER_NETD7_N_2_P044" (solid, remove dead copper, pour order 44): 76.525,62.975 76,63.5 76,68.005 79,68.005 79,62.975
VDC+ on Top Layer "TOP_LAYER_VDC+_P045" (solid, remove dead copper, pour order 45): 67.5,58 67.5,64.5 70,67 72,67 72,63.5 73,62.5 73,60 71,58
NetC213_N_2 on Top Layer "TOP_LAYER_NETC213_N_2_P115" (solid, remove dead copper, pour order 115): 66,46 69,46 76,53 76,57.3 73.3,57.3 72,56 72,52.8 68.8,49.6 66,49.6
GND on Top Layer "TOP_LAYER_GND_P150" (solid, remove dead copper, pour order 150): 97,120.739 102,120.739 102,117.039 98.7,117.039 98.7,117.339 97,119.039
GND on Top Layer "TOP_LAYER_GND_P149" (solid, remove dead copper, pour order 149): 81,120.9 85.8,120.9 85.8,117.9 84.733,116.833 81.894,116.833 81.894,118.146 81,119.039
GND on Top Layer "TOP_LAYER_GND_P148" (solid, remove dead copper, pour order 148): 57.2,121.1 62.8,121.1 62.8,119.239 60.657,117.096 58.1,117.096 58.1,118.539 57.2,119.439
GND on Top Layer "TOP_LAYER_GND_P147" (solid, remove dead copper, pour order 147): 41.9,121.2 46.7,121.2 46.7,119.2 44.505,117.005 42.704,117.005 42.704,118.536 41.9,119.339
+5VISO_PCC on Top Layer "NONET_L-01_P-001" (solid, pour order 145): 103.009,266.3 139.6,266.3 140.1,265.8 140.1,259.826 139.774,259.5 103.5,259.5 102.6,260.4 102.6,265.891
V_PCC_N on Top Layer "NONET_L-01_P-001" (solid, pour order 143): 136.925,260.734 139.35,260.734 139.564,260.52 139.564,259.183 131.276,259.183 130.825,259.634 130.825,260.734 130.927,260.837 132.978,260.837 132.978,259.881 133.111,259.748 136.488,259.748 136.9,260.159 136.897,260.161 136.897,260.73
V_PCC_N on Top Layer "NONET_L-01_P-001" (solid, pour order 142): 122.863,260.603 125.288,260.603 125.876,260.015 125.876,259.051 117.214,259.051 116.763,259.503 116.763,260.603 116.866,260.705 118.917,260.705 118.917,259.749 119.05,259.616 122.427,259.616 122.838,260.028 122.836,260.03 122.836,260.599
NetC75_1 on Top Layer "NONET_L-01_P-001" (solid, pour order 140): 99.608,263.371 101.821,263.371 101.977,263.215 101.977,260.277 101.7,260 99.5,260 99.397,260.103 99.397,263.371
V_PCC_N on Top Layer "NONET_L-01_P-001" (solid, pour order 139): 17 vertices, not listed, extent 105.4,259.149 114.175,260.803
V_PCC_N on Top Layer "NONET_L-01_P-001" (solid, pour order 137): 131.121,263.162 132.84,263.162 132.981,263.021 132.981,260.422 132.721,260.162 131.021,260.162 130.821,260.362 130.821,262.862
V_PCC_N on Top Layer "NONET_L-01_P-001" (solid, pour order 136): 117.059,263.098 118.778,263.098 118.919,262.957 118.919,260.358 118.659,260.098 116.959,260.098 116.759,260.298 116.759,262.798
V_PCC_N on Top Layer "NONET_L-01_P-001" (solid, pour order 135): 105.7,263.2 107.419,263.2 107.56,263.059 107.56,260.46 107.3,260.2 105.6,260.2 105.4,260.4 105.4,262.9
V_PCC_N on Top Layer "NONET_L-01_P-001" (solid, pour order 134): 95.4,263.8 98.7,263.8 98.8,263.7 98.8,262 99.2,261.6 99.2,260.1 99.1,260 95.5,260 95.4,260.1
CAN_GND2 on Top Layer "NONET_L-01_P-001" (solid, pour order 131): 277.8,22.9 278,23.1 282.2,23.1 282.5,22.8 282.5,19.5 282.1,19.1 277.8,19.1 277.2,19.7 277.2,22.3
GND on Top Layer "TOP_LAYER_GND_P128" (solid, remove dead copper, pour order 128): 98,252 101.5,252 101.5,246 99,246 99,249 98,250
NetF2_1 on Top Layer "TOP_LAYER_NETF2_1_P127" (solid, remove dead copper, pour order 127): 230.5,264 230.5,271 241,271 241,264
NetL12_6 on Top Layer "TOP_LAYER_NETL12_6_P126" (solid, remove dead copper, pour order 126): 19 vertices, not listed, extent 154,246 200,280
GND on Top Layer "TOP_LAYER_GND_P107" (solid, remove dead copper, pour order 107): 116,66.3 116,71.3 119.7,71.3 119.7,67.7 119.1,67.7 117.7,66.3
GND on Top Layer "TOP_LAYER_GND_P105" (solid, remove dead copper, pour order 105): 115.5,50.1 115.5,55.1 118.3,55.1 119.2,54.2 119.2,50.6 118.9,50.3 117.7,50.3 117.5,50.1
GND on Top Layer "TOP_LAYER_GND_P104" (solid, remove dead copper, pour order 104): 115.3,26.5 115.3,32.1 117.5,32.1 119,30.6 119,27 118.7,26.7 117.5,26.7 117.3,26.5
GND on Top Layer "TOP_LAYER_GND_P103" (solid, remove dead copper, pour order 103): 115.2,11 115.2,16 118,16 118.9,15.1 118.9,11.5 118.6,11.2 117.4,11.2 117.2,11
5V_S1_GaN_N on Top Layer "TOP_LAYER_5V_S1_GAN_N_P102" (solid, remove dead copper, pour order 102): 104,67.5 104,70 107.6,70 107.8,69.8 107.8,67.5 103.9,67.5
GND_S1_GaN_N on Top Layer "TOP_LAYER_GND_S1_GAN_N_P101" (solid, remove dead copper, pour order 101): 103,66 105.5,66 105.5,67 108,67 108,64 107.5,63.5 105.5,63.5 105,63 103,63
5V_S2_GaN_N on Top Layer "TOP_LAYER_5V_S2_GAN_N_P100" (solid, remove dead copper, pour order 100): 107.5,51.5 107.5,53 105,53 104.5,53.5 104,53.5 104,51.5
GND_S2_GaN_N on Top Layer "TOP_LAYER_GND_S2_GAN_N_P099" (solid, remove dead copper, pour order 99): 105.5,50 105.5,51 107.5,51 107.5,48 107,47.5 103,47.5 103,49.5 105,49.5
5V_S3_GaN_N on Top Layer "TOP_LAYER_5V_S3_GAN_N_P098" (solid, remove dead copper, pour order 98): 107,28 105.5,28 105,27.5 103,27.5 103,30 107,30
GND_S3_GaN_N on Top Layer "TOP_LAYER_GND_S3_GAN_N_P097" (solid, remove dead copper, pour order 97): 105.5,26.5 105.5,27.5 107,27.5 107,24 105,24 105,22.5 103,22.5 103,24 102.5,24.5 102.5,25.5 104.5,25.5 104.5,26.5
5V_S4_GaN_N on Top Layer "TOP_LAYER_5V_S4_GAN_N_P096" (solid, remove dead copper, pour order 96): 103,11.5 103,15.5 107,15.5 107,12.5 105.5,12.5 105,12 105,11.5
GND_S4_GaN_N on Top Layer "TOP_LAYER_GND_S4_GAN_N_P095" (solid, remove dead copper, pour order 95): 106,8.5 106,6.5 103,6.5 103,8.5 102.5,8.5 102.5,10 104,10 105.5,11.5 105.5,12 107,12 107,8.5
PCC_N on Top Layer "TOP_LAYER_PCC_N_P094" (solid, remove dead copper, pour order 94): 263.5,293 271,293 271,270.5 263.5,270.5
PCC_L1 on Top Layer "TOP_LAYER_PCC_L1_P093" (solid, remove dead copper, pour order 93): 243.5,292.5 255,292.5 255,276.5 243.5,276.5
PCC_L2 on Top Layer "TOP_LAYER_PCC_L2_P092" (solid, remove dead copper, pour order 92): 223.5,292.5 230.5,292.5 230.5,284 232,282.5 235.5,282.5 235.5,277 225.5,277 223.5,279
PCC_L3 on Top Layer "TOP_LAYER_PCC_L3_P091" (solid, remove dead copper, pour order 91): 219,283 219,277 204.5,277 203,278.5 203,292.5 211,292.5 211,283
NetF4_1 on Top Layer "TOP_LAYER_NETF4_1_P090" (solid, remove dead copper, pour order 90): 286.5,278 287,277.5 287,271.5 283,267.5 283,263.5 281,261.5 274,261.5 274,278
NetF1_1 on Top Layer "TOP_LAYER_NETF1_1_P086" (solid, remove dead copper, pour order 86): 17 vertices, not listed, extent 240,221 256.5,270.5
V_PCC_L3 on Top Layer "TOP_LAYER_V_PCC_L3_P071" (solid, remove dead copper, pour order 71): 20 vertices, not listed, extent 73,275 173,299.5
I_PCC_L2+ on Top Layer "TOP_LAYER_I_PCC_L2+_P054" (solid, remove dead copper, pour order 54): 106,217 106,209 99,209 99,217
I_PCC_L1- on Top Layer "TOP_LAYER_I_PCC_L1-_P052" (solid, remove dead copper, pour order 52): 50,227 79,227 79,235 82,238 84.9,238 84.9,242.6 61.6,242.6 50,231
VDC-_REF on Top Layer "TOP_LAYER_VDC-_REF_P046" (solid, remove dead copper, pour order 46): 72,7.5 72,11.5 65.5,11.5 63,14 58,14 58,9.5 60,7.5
NetD13_N_1 on Top Layer "TOP_LAYER_NETD13_N_1_P033" (solid, remove dead copper, pour order 33): 88,11.5 87.5,11.5 87.5,13 90,13 90,7.5 88,7.5
NetD13_N_2 on Top Layer "TOP_LAYER_NETD13_N_2_P032" (solid, remove dead copper, pour order 32): 82.5,11.5 85.5,11.5 85.5,7.5 82.5,7.5
NetD14_N_1 on Top Layer "TOP_LAYER_NETD14_N_1_P031" (solid, remove dead copper, pour order 31): 75.5,11.5 78.5,11.5 78.5,7.5 75.5,7.5
I_PCC_N+ on Top Layer "TOP_LAYER_I_PCC_N+_P022" (solid, remove dead copper, pour order 22): 29.5,101.5 23.039,95.039 1.386,95.039 0.251,96.174 0.251,124.344 12,136.093 12,142.16 0,154.16 0,278 16,278 16,152.5 23.5,145 23.5,133.482 15.464,125.446 15.464,115.536
I_PCC_N- on Top Layer "TOP_LAYER_I_PCC_N-_P021" (solid, remove dead copper, pour order 21): 9.5,52 7.5,54 7.5,69 9,70.5 32.5,70.5 33.848,71.848 33.848,97.152 30.25,100.75 15.464,85.964 15.464,82.964 13,80.5 1.5,80.5 1.5,22 7.5,22 9.5,24
SN_LN on Top Layer "TOP_LAYER_SN_LN_P003" (solid, remove dead copper, pour order 3): 72,40 71,39 65.5,39 64.5,40 60,40 55.5,44.5 55.5,52.5 49,52.5 49,23 55,23 55,29 58,32 78,32 78,40
GND on Layer 1 "NONET_L-01_P-001" (solid, pour order 297): 26 vertices, not listed, extent 33,0.6 299.9,121
VDC+ on Layer 1 "Layer 1-VDC+" (solid, pour order 360): 41 vertices, not listed, extent 1,9.5 270,297
GND on Layer 1 "NONET_L-01_P-001" (solid, pour order 298): 41 vertices, not listed, extent 92.9,72.7 299.7,275.5
NetC213_L2_1 on Layer 1 "LAYER_1_NETC213_L2_1_P390" (solid, remove dead copper, pour order 390): 130.661,149 130.661,137.466 132.161,135.966 135.161,135.966 136.661,137.466 136.661,149
NetC213_L3_1 on Layer 1 "LAYER_1_NETC213_L3_1_P391" (solid, remove dead copper, pour order 391): 214.661,121 214.661,115.966 214.661,109.466 216.161,107.966 219.161,107.966 220.661,109.466 220.661,121
NetC213_L1_1 on Layer 1 "LAYER_1_NETC213_L1_1_P389" (solid, remove dead copper, pour order 389): 46.661,164 46.661,158.966 46.661,152.466 48.161,150.966 51.161,150.966 52.661,152.466 52.661,164
NetC213_N_1 on Layer 1 "LAYER_1_NETC213_N_1_P388" (solid, remove dead copper, pour order 388): 72.5,16 77,16 77.5,15.5 84,15.5 85.5,17 85.5,20 84,21.5 72.5,21.5
I_PCC_L3- on Layer 1 "LAYER_1_I_PCC_L3-_P387" (solid, remove dead copper, pour order 387): 218,184 218,190 248.5,190 248.5,184
I_PCC_L2- on Layer 1 "LAYER_1_I_PCC_L2-_P386" (solid, remove dead copper, pour order 386): 129.5,212 129.5,220 163,220 163,212
I_PCC_L1- on Layer 1 "LAYER_1_I_PCC_L1-_P385" (solid, remove dead copper, pour order 385): 50,227 50,231.5 79,231.5 79,227
I_PCC_L3+ on Layer 1 "LAYER_1_I_PCC_L3+_P384" (solid, remove dead copper, pour order 384): 63.5,275 63.5,281.5 44.5,281.5 33,270 33,235 49.5,235 50.5,236 50.5,241 50,241.5 39.5,241.5 38.5,242.5 38.5,261.5 52,275
VDC-_REF on Layer 1 "LAYER_1_VDC-_REF_P379" (solid, remove dead copper, pour order 379): 84,93 84,80 86,78 98,78 98,94 97,95 86,95
PCC_L3 on Layer 1 "LAYER_1_PCC_L3_P372" (solid, remove dead copper, pour order 372): 211,277 204,284 204,292 211,292 211,283 214,280 214,277
PCC_L2 on Layer 1 "LAYER_1_PCC_L2_P370" (solid, remove dead copper, pour order 370): 224,277 224,293 231,293 231,280 231,277 225,277
PCC_L1 on Layer 1 "LAYER_1_PCC_L1_P369" (solid, remove dead copper, pour order 369): 243,277 243,293 251,293 251,282 256,282 256,277
PCC_N on Layer 1 "LAYER_1_PCC_N_P368" (solid, remove dead copper, pour order 368): 263,273 263,293 270,293 270,273
GND_S1_GaN_N on Layer 1 "LAYER_1_GND_S1_GAN_N_P008" (solid, remove dead copper, pour order 8): 20 vertices, not listed, extent 65.768,41.419 107.096,72
GND on Layer 1 "LAYER_1_GND_P209" (solid, remove dead copper, pour order 209): 116,104.502 116.023,104.479 188,104.479 188,96.5 116,96.5 116,104.5
GND_S1_GaN_L2 on Layer 1 "LAYER_1_GND_S1_GAN_L2_P210" (solid, remove dead copper, pour order 210): 20 vertices, not listed, extent 156.244,114.504 186.825,155.832
GND_S3_GaN_L2 on Layer 1 "LAYER_1_GND_S3_GAN_L2_P211" (solid, remove dead copper, pour order 211): 152.642,115.6 152.642,120.827 150.835,122.634 145.825,122.634 145.825,123.589 144.814,124.6 138.704,124.6 138.704,135.27 138.106,135.868 134.07,135.868 130.294,132.092 130.294,126.154 131.848,124.6 131.848,115.6
GND_S2_GaN_L2 on Layer 1 "LAYER_1_GND_S2_GAN_L2_P212" (solid, remove dead copper, pour order 212): 149.825,128.6 149.825,137.6 156.825,137.6 156.825,134.6 158.825,132.6 158.825,125.6 167.804,125.6 169.825,123.579 169.825,115.6 168.825,114.6 156.825,114.6 155.825,115.6 155.825,126.1 154.325,127.6 150.825,127.6
GND on Layer 1 "LAYER_1_GND_P253" (solid, remove dead copper, pour order 253): 200,76.502 200.023,76.479 272,76.479 272,68.5 200,68.5 200,76.5
GND_ISO_CAN on Layer 1 "NONET_L-01_P-001" (solid, pour order 301): 293.1,24.2 295.6,21.7 295.6,14.2 286,4.6 254.7,4.6 250.7,8.6 250.7,16.3 258.6,24.2
GND on Layer 1 "NONET_L-01_P-001" (solid, pour order 300): 188,83.8 192.9,83.8 194.4,82.3 194.4,77.9 188,77.9
GNDP on Layer 1 "NONET_L-01_P-001" (solid, pour order 281): 168.6,28.1 173.945,28.1 188.745,13.3 202.6,13.3 203.4,12.5 203.4,1.7 202.3,0.6 163.9,0.6 163.1,1.4 163.1,18.6 163.994,19.494 167.136,19.494 167.7,20.058 167.7,27.2
GND_S4_GaN_L3 on Layer 1 "LAYER_1_GND_S4_GAN_L3_P257" (solid, remove dead copper, pour order 257): 209.94,121.6 213.825,121.6 216.825,124.6 216.825,128.1 215.715,129.21 210.435,129.21 203.325,122.1 203.325,98.6 199.825,95.1 199.825,86.6 214.325,86.6 214.325,95.1 206.325,103.1 206.325,117.985
GND_S2_GaN_L3 on Layer 1 "LAYER_1_GND_S2_GAN_L3_P256" (solid, remove dead copper, pour order 256): 233.825,100.6 233.825,109.6 240.825,109.6 240.825,106.6 242.825,104.6 242.825,97.6 251.804,97.6 253.825,95.579 253.825,87.6 252.825,86.6 240.825,86.6 239.825,87.6 239.825,98.1 238.325,99.6 234.825,99.6
GND_S3_GaN_L3 on Layer 1 "LAYER_1_GND_S3_GAN_L3_P255" (solid, remove dead copper, pour order 255): 236.642,87.6 236.642,92.827 234.835,94.634 229.825,94.634 229.825,95.589 228.814,96.6 222.704,96.6 222.704,107.27 222.106,107.868 218.07,107.868 214.294,104.092 214.294,98.154 215.848,96.6 215.848,87.6
GND_S1_GaN_L3 on Layer 1 "LAYER_1_GND_S1_GAN_L3_P254" (solid, remove dead copper, pour order 254): 20 vertices, not listed, extent 240.244,86.504 270.825,127.832
GND_S4_GaN_L2 on Layer 1 "LAYER_1_GND_S4_GAN_L2_P213" (solid, remove dead copper, pour order 213): 125.94,149.6 129.825,149.6 132.825,152.6 132.825,156.1 131.817,157.108 126.333,157.108 119.325,150.1 119.325,126.6 115.825,123.1 115.825,114.6 130.325,114.6 130.325,123.1 122.325,131.1 122.325,145.985
GND on Layer 1 "LAYER_1_GND_P169" (solid, remove dead copper, pour order 169): 33,119.479 104,119.479 104,111.5 33,111.5
GND_S1_GaN_L1 on Layer 1 "LAYER_1_GND_S1_GAN_L1_P170" (solid, remove dead copper, pour order 170): 20 vertices, not listed, extent 72.244,129.504 102.825,170.832
GND_S3_GaN_L1 on Layer 1 "LAYER_1_GND_S3_GAN_L1_P171" (solid, remove dead copper, pour order 171): 68.642,130.6 68.642,135.827 66.835,137.634 61.825,137.634 61.825,138.589 60.814,139.6 54.704,139.6 54.704,150.27 54.106,150.868 50.07,150.868 46.294,147.092 46.294,141.154 47.848,139.6 47.848,130.6
GND_S2_GaN_L1 on Layer 1 "LAYER_1_GND_S2_GAN_L1_P172" (solid, remove dead copper, pour order 172): 65.825,143.6 65.825,152.6 72.825,152.6 72.825,149.6 74.825,147.6 74.825,140.6 83.804,140.6 85.825,138.579 85.825,130.6 84.825,129.6 72.825,129.6 71.825,130.6 71.825,141.1 70.325,142.6 66.825,142.6
GND_S4_GaN_L1 on Layer 1 "LAYER_1_GND_S4_GAN_L1_P173" (solid, remove dead copper, pour order 173): 41.94,164.6 45.825,164.6 48.825,167.6 48.825,171.1 47.806,172.119 42.344,172.119 35.325,165.1 35.325,141.6 31.825,138.1 31.825,129.6 46.325,129.6 46.325,138.1 38.325,146.1 38.325,160.985
V_PCC_N on Layer 1 "NONET_L-01_P-001" (solid, pour order 133): 96.8,271.8 139.4,271.8 140.2,271 140.2,259.926 139.674,259.4 95.4,259.4 94.5,260.3 94.5,269.5
CAN_GND2 on Layer 1 "NONET_L-01_P-001" (solid, pour order 132): 278,23.1 282.2,23.1 282.7,22.6 282.7,20.3 285.3,17.7 287.225,17.7 288.2,16.725 288.2,15.7 288.1,15.6 279.1,15.6 277.2,17.5 277.2,22.3
NetL12_2 on Layer 1 "LAYER_1_NETL12_2_P084" (solid, remove dead copper, pour order 84): 190,270 191,269 202,269 237,234 237,221.5 220.5,221.5 220.5,240.1 206.05,254.55 198,254.5 189.5,263 172.5,263 172.412,263.165 172.412,269.912 172.5,270
V_PCC_L1 on Layer 1 "Layer 1-V_PCC_L1" (solid, remove dead copper, pour order 77): 31 vertices, not listed, extent 41,239 179,299
GND_S4_GaN_N on Layer 1 "LAYER_1_GND_S4_GAN_N_P117" (solid, remove dead copper, pour order 117): 72,11.115 72,15 69,18 65.5,18 65,17.5 65,11 71.5,4.5 95,4.5 98.5,1 107,1 107,15.5 98.5,15.5 90.5,7.5 75.615,7.5
GND_S2_GaN_N on Layer 1 "LAYER_1_GND_S2_GAN_N_P114" (solid, remove dead copper, pour order 114): 93,35 84,35 84,42 87,42 89,44 96,44 96,52.979 98.021,55 106,55 107,54 107,42 106,41 95.5,41 94,39.5 94,36
GND_S3_GaN_N on Layer 1 "LAYER_1_GND_S3_GAN_N_P110" (solid, remove dead copper, pour order 110): 106,37.817 100.773,37.817 98.966,36.01 98.966,31 98.011,31 97,29.989 97,23.879 86.33,23.879 85.732,23.281 85.732,19.245 89.508,15.469 95.446,15.469 97,17.023 106,17.023
GND on Layer 1 "LAYER_1_GND_P013" (solid, remove dead copper, pour order 13): 116.998,1 117.021,1.023 117.021,73 125,73 125,1 117,1
NetF2_1 on Layer 1 "LAYER_1_NETF2_1_P088" (solid, remove dead copper, pour order 88): 230.5,271 249.3,271 249.3,263.2 260.5,252 274,252 283.5,242.5 283.5,238.5 274,238.5 272,240.5 268.5,244 258.5,244 240.9,261.6 230.5,261.6
NetL12_4 on Layer 1 "LAYER_1_NETL12_4_P083" (solid, remove dead copper, pour order 83): 18 vertices, not listed, extent 172,216.5 272.25,285

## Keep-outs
Top Layer:
  region: 203.75,183.615 261.75,183.615 261.75,144.615 203.75,144.615
  region: 119.75,211.615 177.75,211.615 177.75,172.615 119.75,172.615
  region: 34.936,226.825 92.936,226.825 92.936,187.825 34.936,187.825
  region: 10,10 10,68 49,68 49,10
Keep-Out Layer:
  text ".Layer_Name" at -20.344,-20.806 h1.52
